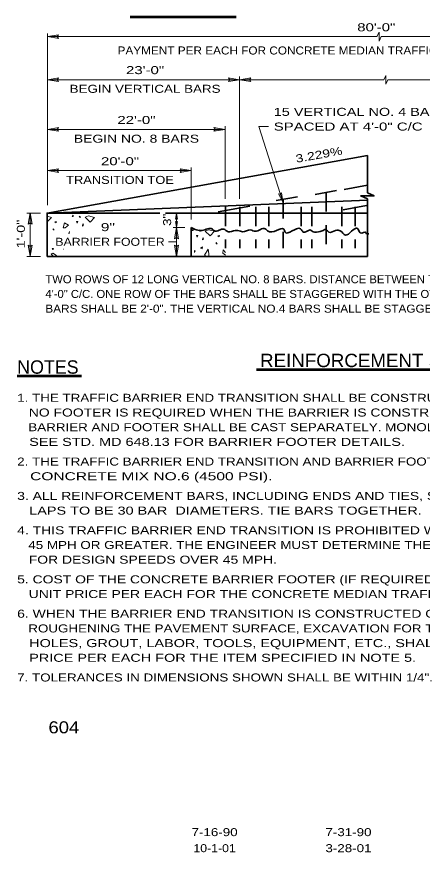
# Model space of a CAD drawing. Extents: x -11.7 to -4.5, y 8.6 to 18.8.
# Drawn here: x -11.75 to -8.7, y 8.81 to 15.07 of the extents above; entities that cross this region are included whole.
import ezdxf
from ezdxf.enums import TextEntityAlignment as Align

# ---------------------------------------------------------------- set-up
doc = ezdxf.new("R2010")
doc.units = 0
doc.header["$LTSCALE"] = 0.024
doc.linetypes.add('LONG_DASHED', pattern=[7.5, 6, -1.5])
for name, color, linetype, lineweight in [('1', 7, 'Continuous', 35), ('10', 7, 'Continuous', 13), ('12', 7, 'Continuous', 53), ('13', 7, 'Continuous', 53), ('6', 7, 'Continuous', 13)]:
    doc.layers.add(name, color=color, linetype=linetype, lineweight=lineweight)

msp = doc.modelspace()

# ---------------------------------------------------------------- hatches: boundary and pattern name
at = {"layer": '10'}
for points in [[(-11.51467, 14.919), (-11.43067, 14.905), (-11.44117, 14.919), (-11.43067, 14.933)], [(-11.51467, 14.59633), (-11.43067, 14.58233), (-11.44117, 14.59633), (-11.43067, 14.61033)], [(-10.07367, 14.59633), (-10.15767, 14.58233), (-10.14717, 14.59633), (-10.15767, 14.61033)], [(-10.07367, 14.59633), (-9.98967, 14.61033), (-10.00017, 14.59633), (-9.98967, 14.58233)], [(-11.51467, 14.22467), (-11.43067, 14.21067), (-11.44117, 14.22467), (-11.43067, 14.23867)], [(-10.18217, 14.22467), (-10.26617, 14.21067), (-10.25567, 14.22467), (-10.26617, 14.23867)], [(-11.51467, 13.916), (-11.43067, 13.902), (-11.44117, 13.916), (-11.43067, 13.93)], [(-10.43683, 13.916), (-10.52083, 13.902), (-10.51017, 13.916), (-10.52083, 13.93)], [(-11.6305, 13.51433), (-11.6445, 13.59833), (-11.6585, 13.51433), (-11.6445, 13.52467)], [(-10.53983, 13.55233), (-10.54733, 13.558), (-10.55483, 13.55233), (-10.54733, 13.59733)], [(-10.53983, 13.53383), (-10.54733, 13.48883), (-10.55483, 13.53383), (-10.54733, 13.52833)], [(-10.53333, 13.40483), (-10.54733, 13.48883), (-10.56133, 13.40483), (-10.54733, 13.41533)], [(-11.6445, 13.2745), (-11.6305, 13.3585), (-11.6445, 13.348), (-11.6585, 13.3585)], [(-10.54733, 13.27333), (-10.53333, 13.35733), (-10.54733, 13.34683), (-10.56133, 13.35733)]]:
    msp.add_hatch(color=256, dxfattribs=at).paths.add_polyline_path(points)

# ---------------------------------------------------------------- linework, layer by layer
at = {"layer": '1'}
for p, q in [((-9.29017, 13.77467), (-9.11417, 13.80633)), ((-9.801, 13.69117), (-9.63867, 13.7205)), ((-9.50833, 13.73717), (-9.3465, 13.76633)), ((-11.518, 13.59733), (-9.11217, 13.6955)), ((-10.23367, 13.60767), (-9.99783, 13.65)), ((-9.2975, 13.62233), (-9.1215, 13.654)), ((-11.518, 13.59733), (-10.67267, 13.59733)), ((-10.63017, 13.59733), (-9.11417, 13.59733)), ((-10.43783, 13.27333), (-9.11467, 13.27333))]:
    msp.add_line(p, q, dxfattribs=at)
at = {"layer": '1', "linetype": 'LONG_DASHED'}
for p, q in [((-9.42383, 13.75233), (-9.42383, 13.33583)), ((-10.17983, 13.64333), (-10.17983, 13.33583)), ((-10.07183, 13.64333), (-10.07183, 13.33583)), ((-9.95117, 13.64333), (-9.95117, 13.33583)), ((-9.85583, 13.64333), (-9.85583, 13.33583)), ((-9.74783, 13.70083), (-9.74783, 13.33583)), ((-9.61117, 13.64333), (-9.61117, 13.33583)), ((-9.53183, 13.64333), (-9.53183, 13.33583)), ((-9.30617, 13.64333), (-9.30617, 13.33583)), ((-9.20783, 13.64333), (-9.20783, 13.33583))]:
    msp.add_line(p, q, dxfattribs=at)
at = {"layer": '1'}
for points in [[(-11.518, 13.27333), (-11.518, 13.59733), (-9.11467, 14.0295)], [(-11.518, 13.27333), (-10.43783, 13.27333), (-10.43783, 13.48933)]]:
    msp.add_lwpolyline(points, dxfattribs=at)
msp.add_spline([(-10.43783, 13.48933), (-10.35467, 13.46783), (-10.27817, 13.47733), (-10.26217, 13.4645), (-10.19217, 13.47733), (-10.16017, 13.45817), (-10.106, 13.46783), (-10.06783, 13.46133), (-10.05183, 13.45817), (-9.99133, 13.471), (-9.95633, 13.46133), (-9.883, 13.4805), (-9.86383, 13.4645), (-9.797, 13.46783), (-9.74267, 13.47733), (-9.73317, 13.455), (-9.6185, 13.4805), (-9.6025, 13.46133), (-9.59617, 13.455), (-9.54517, 13.471), (-9.51317, 13.455), (-9.51017, 13.455), (-9.456, 13.4645), (-9.42717, 13.47417), (-9.40483, 13.455), (-9.35383, 13.46783), (-9.31883, 13.4645), (-9.28067, 13.43267), (-9.19133, 13.48367), (-9.1755, 13.45817), (-9.169, 13.44867), (-9.12767, 13.45183), (-9.12767, 13.44867), (-9.118, 13.44217), (-9.10533, 13.44217)], degree=3, dxfattribs=at)
at = {"layer": '10'}
for p, q in [((-11.51467, 13.65733), (-11.51467, 14.943)), ((-11.43067, 14.933), (-11.51467, 14.919)), ((-11.51467, 14.919), (-9.0435, 14.919)), ((-11.43067, 14.905), (-11.51467, 14.919)), ((-11.43067, 14.933), (-11.44117, 14.919)), ((-11.43067, 14.905), (-11.44117, 14.919)), ((-6.8805, 14.919), (-9.01333, 14.919)), ((-11.43067, 14.61033), (-11.51467, 14.59633)), ((-11.51467, 14.59633), (-10.07367, 14.59633)), ((-11.43067, 14.58233), (-11.51467, 14.59633)), ((-11.43067, 14.61033), (-11.44117, 14.59633)), ((-11.43067, 14.58233), (-11.44117, 14.59633)), ((-10.15767, 14.61033), (-10.07367, 14.59633)), ((-10.15767, 14.61033), (-10.14717, 14.59633)), ((-10.15767, 14.58233), (-10.07367, 14.59633)), ((-10.15767, 14.58233), (-10.14717, 14.59633)), ((-10.07367, 13.70333), (-10.07367, 14.62033)), ((-9.98967, 14.61033), (-10.07367, 14.59633)), ((-10.07367, 14.59633), (-8.992, 14.59633)), ((-9.98967, 14.58233), (-10.07367, 14.59633)), ((-9.98967, 14.61033), (-10.00017, 14.59633)), ((-9.98967, 14.58233), (-10.00017, 14.59633)), ((-6.98233, 14.59633), (-8.962, 14.59633)), ((-11.43067, 14.23867), (-11.51467, 14.22467)), ((-11.51467, 14.22467), (-10.18217, 14.22467)), ((-11.43067, 14.21067), (-11.51467, 14.22467)), ((-11.43067, 14.23867), (-11.44117, 14.22467)), ((-11.43067, 14.21067), (-11.44117, 14.22467)), ((-10.26617, 14.23867), (-10.18217, 14.22467)), ((-10.26617, 14.23867), (-10.25567, 14.22467)), ((-10.26617, 14.21067), (-10.18217, 14.22467)), ((-10.26617, 14.21067), (-10.25567, 14.22467)), ((-10.18217, 13.70333), (-10.18217, 14.24867)), ((-9.9305, 14.24567), (-9.75017, 13.68233)), ((-9.858, 14.24567), (-9.9305, 14.24567)), ((-11.43067, 13.93), (-11.51467, 13.916)), ((-11.51467, 13.916), (-10.43683, 13.916)), ((-11.43067, 13.902), (-11.51467, 13.916)), ((-11.43067, 13.93), (-11.44117, 13.916)), ((-11.43067, 13.902), (-11.44117, 13.916)), ((-10.52083, 13.93), (-10.43683, 13.916)), ((-10.52083, 13.93), (-10.51017, 13.916)), ((-10.52083, 13.902), (-10.43683, 13.916)), ((-10.52083, 13.902), (-10.51017, 13.916)), ((-10.43683, 13.54933), (-10.43683, 13.94)), ((-9.78133, 13.74283), (-9.75017, 13.68233)), ((-9.78133, 13.74283), (-9.768, 13.73833)), ((-9.76, 13.74967), (-9.768, 13.73833)), ((-9.76, 13.74967), (-9.75017, 13.68233)), ((-11.566, 13.598), (-11.6685, 13.598)), ((-11.6585, 13.51433), (-11.6445, 13.59833)), ((-11.6445, 13.2745), (-11.6445, 13.59833)), ((-11.6305, 13.51433), (-11.6445, 13.59833)), ((-10.55483, 13.55233), (-10.54733, 13.59733)), ((-10.54733, 13.48883), (-10.54733, 13.59733)), ((-10.53983, 13.55233), (-10.54733, 13.59733)), ((-11.6585, 13.51433), (-11.6445, 13.52467)), ((-11.6305, 13.51433), (-11.6445, 13.52467)), ((-10.55483, 13.55233), (-10.54733, 13.558)), ((-10.55483, 13.53383), (-10.54733, 13.48883)), ((-10.55483, 13.53383), (-10.54733, 13.52833)), ((-10.53983, 13.55233), (-10.54733, 13.558)), ((-10.53983, 13.53383), (-10.54733, 13.48883)), ((-10.53983, 13.53383), (-10.54733, 13.52833)), ((-10.48583, 13.48883), (-10.57133, 13.48883)), ((-10.56133, 13.40483), (-10.54733, 13.48883)), ((-10.54733, 13.48883), (-10.54733, 13.27333)), ((-10.53333, 13.40483), (-10.54733, 13.48883)), ((-10.56133, 13.40483), (-10.54733, 13.41533)), ((-10.53333, 13.40483), (-10.54733, 13.41533)), ((-11.6585, 13.3585), (-11.6445, 13.2745)), ((-11.6585, 13.3585), (-11.6445, 13.348)), ((-11.6305, 13.3585), (-11.6445, 13.2745)), ((-11.6305, 13.3585), (-11.6445, 13.348)), ((-10.54733, 13.38267), (-10.60683, 13.38267)), ((-10.56133, 13.35733), (-10.54733, 13.27333)), ((-10.56133, 13.35733), (-10.54733, 13.34683)), ((-10.53333, 13.35733), (-10.54733, 13.27333)), ((-10.53333, 13.35733), (-10.54733, 13.34683)), ((-11.566, 13.273), (-11.6685, 13.273))]:
    msp.add_line(p, q, dxfattribs=at)
at = {"layer": '10', "lineweight": 35}
for p, q in [((-9.11467, 14.0295), (-9.11467, 13.74983)), ((-9.11467, 13.27333), (-9.11467, 13.70383))]:
    msp.add_line(p, q, dxfattribs=at)
at = {"layer": '10'}
for points in [[(-11.51467, 14.919), (-11.43067, 14.905), (-11.44117, 14.919), (-11.43067, 14.933)], [(-11.51467, 14.59633), (-11.43067, 14.58233), (-11.44117, 14.59633), (-11.43067, 14.61033)], [(-10.07367, 14.59633), (-10.15767, 14.58233), (-10.14717, 14.59633), (-10.15767, 14.61033)], [(-10.07367, 14.59633), (-9.98967, 14.61033), (-10.00017, 14.59633), (-9.98967, 14.58233)], [(-11.51467, 14.22467), (-11.43067, 14.21067), (-11.44117, 14.22467), (-11.43067, 14.23867)], [(-10.18217, 14.22467), (-10.26617, 14.21067), (-10.25567, 14.22467), (-10.26617, 14.23867)], [(-11.51467, 13.916), (-11.43067, 13.902), (-11.44117, 13.916), (-11.43067, 13.93)], [(-10.43683, 13.916), (-10.52083, 13.902), (-10.51017, 13.916), (-10.52083, 13.93)], [(-11.6305, 13.51433), (-11.6445, 13.59833), (-11.6585, 13.51433), (-11.6445, 13.52467)], [(-10.53983, 13.55233), (-10.54733, 13.558), (-10.55483, 13.55233), (-10.54733, 13.59733)], [(-10.53983, 13.53383), (-10.54733, 13.48883), (-10.55483, 13.53383), (-10.54733, 13.52833)], [(-10.53333, 13.40483), (-10.54733, 13.48883), (-10.56133, 13.40483), (-10.54733, 13.41533)], [(-11.6445, 13.2745), (-11.6305, 13.3585), (-11.6445, 13.348), (-11.6585, 13.3585)], [(-10.54733, 13.27333), (-10.53333, 13.35733), (-10.54733, 13.34683), (-10.56133, 13.35733)]]:
    msp.add_lwpolyline(points, close=True, dxfattribs=at)
for points in [[(-9.01317, 14.91933), (-9.028, 14.8855), (-9.0285, 14.9515), (-9.04383, 14.91933)], [(-8.96217, 14.596), (-8.977, 14.56233), (-8.9775, 14.62833), (-8.99283, 14.596)]]:
    msp.add_lwpolyline(points, dxfattribs=at)
at = {"layer": '10', "lineweight": 35}
msp.add_lwpolyline([(-9.11433, 13.70317), (-9.16583, 13.72567), (-9.06517, 13.72633), (-9.11433, 13.74967)], dxfattribs=at)
at = {"layer": '12'}
for p, q in [((-10.8945, 15.06833), (-10.09867, 15.06833)), ((-9.947, 12.42533), (-7.561, 12.42533))]:
    msp.add_line(p, q, dxfattribs=at)
at = {"layer": '13'}
msp.add_line((-11.74183, 12.37767), (-11.25933, 12.37767), dxfattribs=at)
at = {"layer": '6'}
for points in [[(-11.39967, 13.59733), (-11.39733, 13.59333), (-11.39633, 13.59733)], [(-11.518, 13.57417), (-11.48417, 13.5655), (-11.518, 13.5315)], [(-11.45133, 13.27333), (-11.44583, 13.28033), (-11.474, 13.2965), (-11.4865, 13.29083), (-11.47033, 13.27333)], [(-11.39467, 13.32817), (-11.3915, 13.32683), (-11.39183, 13.32817)], [(-10.3135, 13.27333), (-10.336, 13.28317), (-10.30967, 13.32767), (-10.30583, 13.29317), (-10.30417, 13.27333)], [(-10.17983, 13.302), (-10.1805, 13.30333), (-10.19683, 13.3235), (-10.20067, 13.2975), (-10.17983, 13.2825)]]:
    msp.add_lwpolyline(points, dxfattribs=at)
for points in [[(-11.32283, 13.58133), (-11.32867, 13.57117), (-11.32283, 13.57117)], [(-11.46017, 13.53283), (-11.45, 13.52467), (-11.44817, 13.53467)], [(-11.3815, 13.48617), (-11.357, 13.50683), (-11.38717, 13.52467), (-11.39733, 13.48617)], [(-11.2965, 13.53467), (-11.29267, 13.52267), (-11.28633, 13.53467)], [(-11.27, 13.5655), (-11.26617, 13.56733), (-11.27633, 13.5755)], [(-11.24983, 13.517), (-11.25233, 13.50067), (-11.24417, 13.50883)], [(-11.20767, 13.5775), (-11.161, 13.5655), (-11.19567, 13.53083), (-11.23217, 13.56733)], [(-11.47217, 13.4805), (-11.47217, 13.47417), (-11.464, 13.4685)], [(-11.355, 13.444), (-11.35317, 13.444), (-11.34933, 13.46033)], [(-10.423, 13.477), (-10.42867, 13.467), (-10.423, 13.467)], [(-10.37017, 13.46117), (-10.36633, 13.46317), (-10.37633, 13.47133)], [(-10.30767, 13.47317), (-10.26117, 13.46117), (-10.29567, 13.42667), (-10.33217, 13.46317)], [(-10.3965, 13.4305), (-10.39267, 13.4185), (-10.3865, 13.4305)], [(-10.35, 13.41267), (-10.35233, 13.39633), (-10.34417, 13.4045)], [(-10.23717, 13.4285), (-10.227, 13.42033), (-10.22517, 13.4305)], [(-11.48033, 13.33117), (-11.474, 13.32483), (-11.47017, 13.33117)], [(-10.36633, 13.33583), (-10.35433, 13.32967), (-10.35233, 13.344)], [(-10.24917, 13.37617), (-10.24917, 13.37), (-10.241, 13.36417)], [(-10.41283, 13.31767), (-10.41283, 13.30333), (-10.40667, 13.3115)]]:
    msp.add_lwpolyline(points, close=True, dxfattribs=at)

# ---------------------------------------------------------------- texts
at = {"layer": '12'}
for s, height, width, p in [('80\'-0"', 0.06001, 1.4, (-9.049, 14.95925)), ('PAYMENT PER EACH FOR CONCRETE MEDIAN TRAFFIC BARRIER END TRANSITION', 0.06, 1.1, (-9.19642, 14.78542)), ('23\'-0"', 0.06001, 1.4, (-10.78267, 14.63833)), ('BEGIN VERTICAL BARS', 0.06001, 1.25, (-10.78267, 14.49833)), ('22\'-0"', 0.06001, 1.4, (-10.84742, 14.26467)), ('BEGIN NO. 8 BARS', 0.06001, 1.3, (-10.84737, 14.12467)), ('20\'-0"', 0.06001, 1.4, (-10.9705, 13.956)), ('TRANSITION TOE', 0.06001, 1.2, (-10.97054, 13.816)), ('9" ', 0.06001, 1.45, (-11.04558, 13.46267)), ('BARRIER FOOTER', 0.06001, 1.15, (-11.04558, 13.35267)), ('REINFORCEMENT STEEL DETAILS', 0.1, 1.05, (-8.754, 12.44392))]:
    msp.add_text(s, height=height, dxfattribs=dict(at, width=width)).set_placement(p, align=Align.CENTER)
for s, width, p in [('15 VERTICAL NO. 4 BARS', 1.35, (-9.818, 14.32567)), ('SPACED AT 4\'-0" C/C', 1.4, (-9.818, 14.21558)), ('TWO ROWS OF 12 LONG VERTICAL NO. 8 BARS. DISTANCE BETWEEN THE BARS IN EACH ROW SHALL BE', 1.05, (-11.5305, 13.072)), ('4\'-0" C/C. ONE ROW OF THE BARS SHALL BE STAGGERED WITH THE OTHER. CENTER LINE DISTANCE BETWEEN THE', 1.05, (-11.5305, 12.962)), ('BARS SHALL BE 2\'-0". THE VERTICAL NO.4 BARS SHALL BE STAGGERED WITH THE NO.8 BARS (SEE BAR LAYOUT)', 1.1, (-11.5305, 12.852))]:
    msp.add_text(s, height=0.06001, dxfattribs=dict(at, width=width)).set_placement(p)
for s, height, rotation, width, p in [('3.229%', 0.06, 10.192, 1.3, (-9.47364, 14.00545)), ('3"', 0.06001, 90, 1.25, (-10.58733, 13.54692)), ('1\'-0"', 0.06001, 90, 1.35, (-11.6845, 13.44058))]:
    msp.add_text(s, height=height, rotation=rotation, dxfattribs=dict(at, width=width)).set_placement(p, align=Align.CENTER)
at = {"layer": '13'}
msp.add_text('NOTES', height=0.1, dxfattribs=at).set_placement((-11.74175, 12.39475))
for s, width, p in [('1. THE TRAFFIC BARRIER END TRANSITION SHALL BE CONSTRUCTED USING THE FIXED FORM METHOD.', 1.25, (-11.74175, 12.18408)), ('   NO FOOTER IS REQUIRED WHEN THE BARRIER IS CONSTRUCTED ON EXISTING RIGID PAVEMENT.', 1.3, (-11.74175, 12.07408)), ('   BARRIER AND FOOTER SHALL BE CAST SEPARATELY. MONOLITHIC PLACEMENT NOT PERMITTED.', 1.25, (-11.74175, 11.96408)), ('   SEE STD. MD 648.13 FOR BARRIER FOOTER DETAILS.', 1.35, (-11.74175, 11.85408)), ('2. THE TRAFFIC BARRIER END TRANSITION AND BARRIER FOOTER SHALL BE CONSTRUCTED USING', 1.25, (-11.74175, 11.70675)), ('   CONCRETE MIX NO.6 (4500 PSI).', 1.45, (-11.74175, 11.59675)), ('3. ALL REINFORCEMENT BARS, INCLUDING ENDS AND TIES, SHALL BE EPOXY COATED. ALL BAR', 1.3, (-11.74183, 11.44933)), ('   LAPS TO BE 30 BAR  DIAMETERS. TIE BARS TOGETHER.', 1.35, (-11.74183, 11.33933)), ('4. THIS TRAFFIC BARRIER END TRANSITION IS PROHIBITED WHEN THE DESIGN SPEED IS', 1.3, (-11.74183, 11.19192)), ('   45 MPH OR GREATER. THE ENGINEER MUST DETERMINE THE TYPE OF END TREATMENT', 1.25, (-11.74183, 11.08192)), ('   FOR DESIGN SPEEDS OVER 45 MPH.', 1.3, (-11.74183, 10.97192)), ('5. COST OF THE CONCRETE BARRIER FOOTER (IF REQUIRED) SHALL BE INCIDENTAL TO THE CONTRACT', 1.3, (-11.74192, 10.8245)), ('   UNIT PRICE PER EACH FOR THE CONCRETE MEDIAN TRAFFIC BARRIER END TRANSITION.', 1.3, (-11.74192, 10.7145)), ('6. WHEN THE BARRIER END TRANSITION IS CONSTRUCTED ON EXISTING RIGID PAVEMENT THE COST OF ', 1.3, (-11.74192, 10.56708)), ('   ROUGHENING THE PAVEMENT SURFACE, EXCAVATION FOR TRANSITION TOE, REINFORCEMENT, DRILLED ', 1.25, (-11.74192, 10.45708)), ('   HOLES, GROUT, LABOR, TOOLS, EQUIPMENT, ETC., SHALL BE INCIDENTAL TO THE CONTRACT UNIT', 1.35, (-11.74192, 10.34708)), ('   PRICE PER EACH FOR THE ITEM SPECIFIED IN NOTE 5.', 1.35, (-11.74192, 10.23708)), ('7. TOLERANCES IN DIMENSIONS SHOWN SHALL BE WITHIN 1/4".', 1.25, (-11.74192, 10.08967))]:
    msp.add_text(s, height=0.06001, dxfattribs=dict(at, width=width)).set_placement(p)
for s, height, width, p in [('604', 0.09001, 1.15, (-11.39179, 9.7015)), ('7-16-90', 0.06, 1.25, (-10.26158, 8.93133)), ('7-31-90', 0.06, 1.25, (-9.25758, 8.93133)), ('10-1-01', 0.06, 1.15, (-10.26158, 8.81133)), ('3-28-01', 0.06, 1.25, (-9.25762, 8.81133))]:
    msp.add_text(s, height=height, dxfattribs=dict(at, width=width)).set_placement(p, align=Align.CENTER)

doc.saveas('drawing.dxf')
